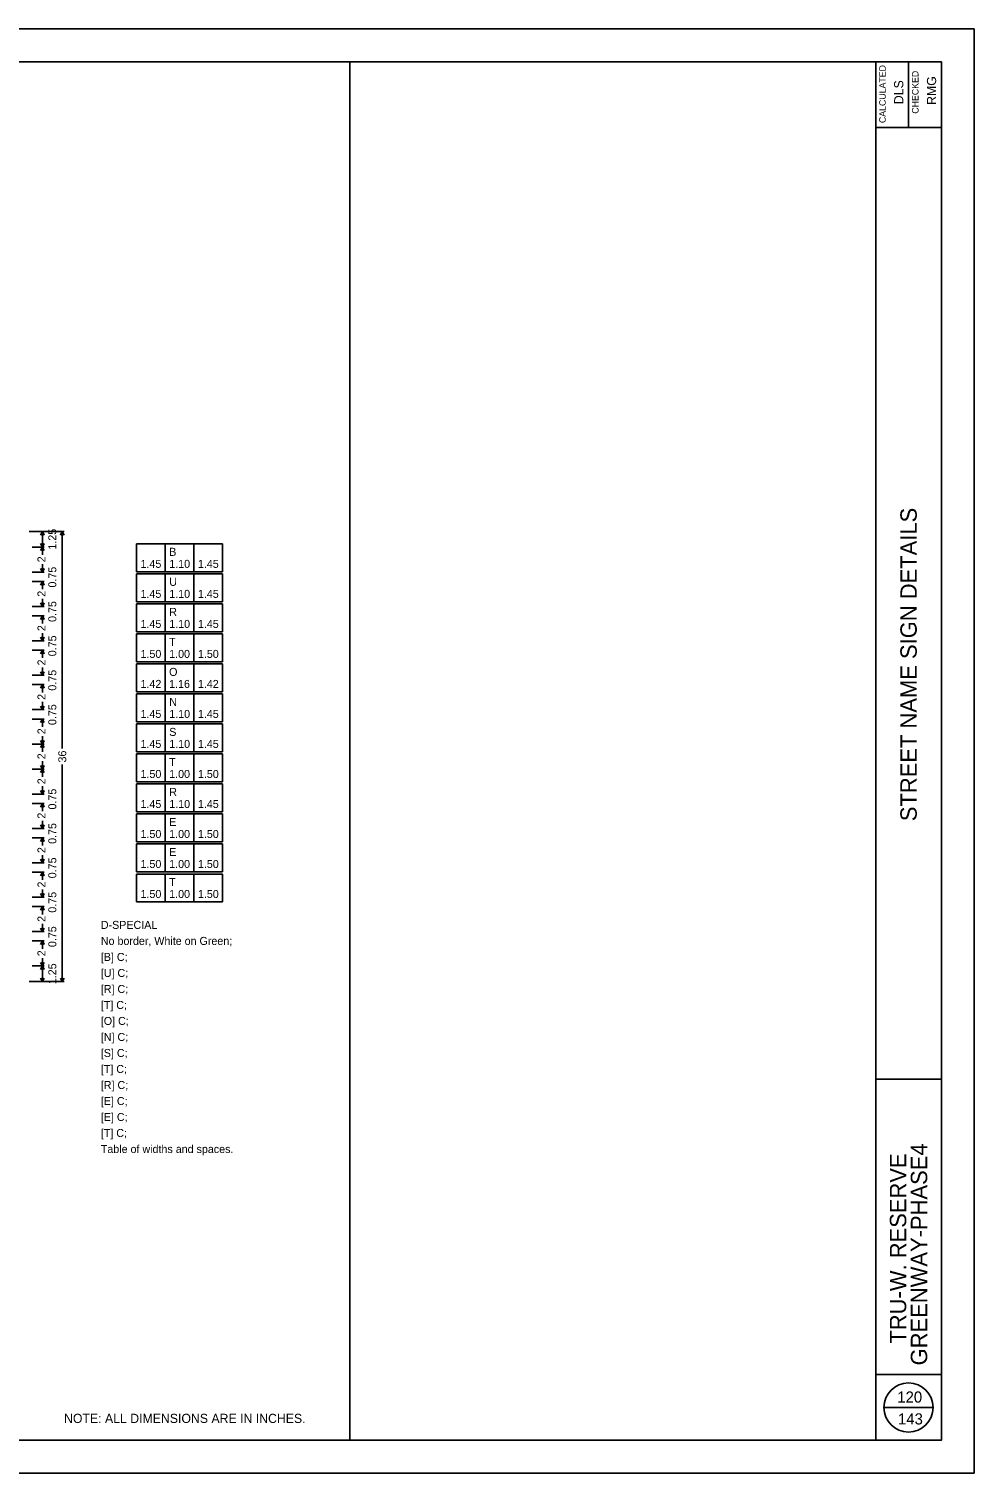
# Model space of a CAD drawing. Extents: x -16.4 to 26.5, y -12.9 to 9.1.
# Drawn here: x 3.22 to 17.63, y -12.91 to 9.09 of the extents above; entities that cross this region are included whole.
import ezdxf

# ---------------------------------------------------------------- set-up
doc = ezdxf.new("R2010")
doc.units = 0
for name, color, linetype in [('PM_P_Text', 7, 'Continuous'), ('SH_Border', 7, 'Continuous'), ('SH_Cut_Line', 7, 'Continuous'), ('SH_Data', 7, 'Continuous'), ('SH_Text', 7, 'Continuous')]:
    doc.layers.add(name, color=color, linetype=linetype)

msp = doc.modelspace()

# ---------------------------------------------------------------- linework, layer by layer
at = {"layer": 'SH_Border'}
for p, q in [((16.129, -12.407), (16.129, 8.593)), ((16.629, 8.593), (16.629, 7.593)), ((16.129, 7.593), (17.129, 7.593)), ((16.129, -6.907), (17.129, -6.907)), ((16.129, -11.407), (17.129, -11.407))]:
    msp.add_line(p, q, dxfattribs=at)
msp.add_lwpolyline([(-14.371, 8.593), (17.129, 8.593), (17.129, -12.407), (-14.371, -12.407)], close=True, dxfattribs=at)
at = {"layer": 'SH_Cut_Line'}
msp.add_lwpolyline([(-16.371, -12.907), (17.629, -12.907), (17.629, 9.093), (-16.371, 9.093)], close=True, dxfattribs=at)
at = {"layer": 'SH_Data'}
msp.add_line((16.254, -11.907), (17.004, -11.907), dxfattribs=at)
msp.add_circle((16.629, -11.907), 0.375, dxfattribs=at)
at = {"layer": 'SH_Text'}
for p, q in [((8.11, -12.407), (8.11, 8.593)), ((3.758, 1.438), (3.224, 1.438)), ((3.453, 1.438), (3.27, 1.438)), ((3.395, 1.383), (3.423, 1.438)), ((3.423, 1.318), (3.423, 1.438)), ((3.45, 1.383), (3.423, 1.438)), ((3.7, 1.383), (3.727, 1.438)), ((3.727, -1.87), (3.727, 1.438)), ((3.755, 1.383), (3.727, 1.438)), ((3.453, 1.199), (3.27, 1.199)), ((3.395, 1.254), (3.423, 1.199)), ((3.395, 1.145), (3.423, 1.199)), ((3.423, 1.318), (3.423, 1.199)), ((3.45, 1.254), (3.423, 1.199)), ((3.423, 1.081), (3.423, 1.199)), ((3.45, 1.145), (3.423, 1.199)), ((4.859, 1.249), (4.859, 0.822)), ((6.172, 1.249), (4.859, 1.249)), ((5.297, 1.249), (5.297, 0.822)), ((5.734, 1.249), (5.734, 0.822)), ((6.172, 1.249), (6.172, 0.822)), ((3.423, 0.937), (3.423, 0.818)), ((3.453, 0.818), (3.27, 0.818)), ((3.453, 0.676), (3.27, 0.676)), ((3.395, 0.873), (3.423, 0.818)), ((3.395, 0.621), (3.423, 0.676)), ((3.45, 0.873), (3.423, 0.818)), ((3.423, 0.557), (3.423, 0.676)), ((3.45, 0.621), (3.423, 0.676)), ((6.172, 0.822), (4.859, 0.822)), ((4.859, 0.791), (4.859, 0.365)), ((6.172, 0.791), (4.859, 0.791)), ((5.297, 0.791), (5.297, 0.365)), ((5.734, 0.791), (5.734, 0.365)), ((6.172, 0.791), (6.172, 0.365)), ((3.453, 0.295), (3.27, 0.295)), ((3.395, 0.349), (3.423, 0.295)), ((3.423, 0.413), (3.423, 0.295)), ((3.45, 0.349), (3.423, 0.295)), ((6.172, 0.365), (4.859, 0.365)), ((4.859, 0.334), (4.859, -0.092)), ((6.172, 0.334), (4.859, 0.334)), ((5.297, 0.334), (5.297, -0.092)), ((5.734, 0.334), (5.734, -0.092)), ((6.172, 0.334), (6.172, -0.092)), ((3.453, 0.152), (3.27, 0.152)), ((3.395, 0.097), (3.423, 0.152)), ((3.423, 0.033), (3.423, 0.152)), ((3.45, 0.097), (3.423, 0.152)), ((3.395, -0.175), (3.423, -0.229)), ((3.423, -0.111), (3.423, -0.229)), ((3.45, -0.175), (3.423, -0.229)), ((6.172, -0.092), (4.859, -0.092)), ((4.859, -0.123), (4.859, -0.55)), ((6.171, -0.123), (4.859, -0.123)), ((5.296, -0.123), (5.296, -0.55)), ((5.734, -0.123), (5.734, -0.55)), ((6.171, -0.123), (6.171, -0.55)), ((3.453, -0.229), (3.27, -0.229)), ((3.453, -0.372), (3.27, -0.372)), ((3.395, -0.427), (3.423, -0.372)), ((3.423, -0.49), (3.423, -0.372)), ((3.45, -0.427), (3.423, -0.372)), ((3.423, -0.635), (3.423, -0.753)), ((6.171, -0.55), (4.859, -0.55)), ((4.859, -0.58), (4.859, -1.007)), ((6.171, -0.58), (4.859, -0.58)), ((5.295, -0.58), (5.295, -1.007)), ((5.734, -0.58), (5.734, -1.007)), ((6.171, -0.58), (6.171, -1.007)), ((3.453, -0.753), (3.27, -0.753)), ((3.395, -0.699), (3.423, -0.753)), ((3.45, -0.699), (3.423, -0.753)), ((3.453, -0.896), (3.27, -0.896)), ((3.395, -0.951), (3.423, -0.896)), ((3.423, -1.014), (3.423, -0.896)), ((3.45, -0.951), (3.423, -0.896)), ((6.171, -1.007), (4.859, -1.007)), ((4.859, -1.037), (4.859, -1.464)), ((6.172, -1.037), (4.859, -1.037)), ((5.297, -1.037), (5.297, -1.464)), ((5.734, -1.037), (5.734, -1.464)), ((6.172, -1.037), (6.172, -1.464)), ((3.453, -1.277), (3.27, -1.277)), ((3.395, -1.223), (3.423, -1.277)), ((3.423, -1.159), (3.423, -1.277)), ((3.45, -1.223), (3.423, -1.277)), ((3.453, -1.42), (3.27, -1.42)), ((3.395, -1.474), (3.423, -1.42)), ((3.423, -1.538), (3.423, -1.42)), ((3.45, -1.474), (3.423, -1.42)), ((6.172, -1.464), (4.859, -1.464)), ((4.859, -1.495), (4.859, -1.921)), ((6.172, -1.495), (4.859, -1.495)), ((5.297, -1.495), (5.297, -1.921)), ((5.734, -1.495), (5.734, -1.921)), ((6.172, -1.495), (6.172, -1.921)), ((3.395, -1.746), (3.423, -1.801)), ((3.423, -1.683), (3.423, -1.801)), ((3.45, -1.746), (3.423, -1.801)), ((3.453, -1.801), (3.27, -1.801)), ((3.395, -1.855), (3.423, -1.801)), ((3.423, -1.919), (3.423, -1.801)), ((3.45, -1.855), (3.423, -1.801)), ((6.172, -1.921), (4.859, -1.921)), ((4.859, -1.952), (4.859, -2.378)), ((6.171, -1.952), (4.859, -1.952)), ((5.296, -1.952), (5.296, -2.378)), ((5.734, -1.952), (5.734, -2.378)), ((6.171, -1.952), (6.171, -2.378)), ((3.453, -2.182), (3.27, -2.182)), ((3.395, -2.127), (3.423, -2.182)), ((3.395, -2.236), (3.423, -2.182)), ((3.423, -2.064), (3.423, -2.182)), ((3.45, -2.127), (3.423, -2.182)), ((3.423, -2.3), (3.423, -2.182)), ((3.45, -2.236), (3.423, -2.182)), ((3.727, -2.113), (3.727, -5.42)), ((6.171, -2.378), (4.859, -2.378)), ((4.859, -2.409), (4.859, -2.836)), ((6.172, -2.409), (4.859, -2.409)), ((5.297, -2.409), (5.297, -2.836)), ((5.734, -2.409), (5.734, -2.836)), ((6.172, -2.409), (6.172, -2.836)), ((3.453, -2.563), (3.27, -2.563)), ((3.395, -2.508), (3.423, -2.563)), ((3.423, -2.445), (3.423, -2.563)), ((3.45, -2.508), (3.423, -2.563)), ((3.453, -2.706), (3.27, -2.706)), ((3.395, -2.76), (3.423, -2.706)), ((3.423, -2.824), (3.423, -2.706)), ((3.45, -2.76), (3.423, -2.706)), ((6.172, -2.836), (4.859, -2.836)), ((3.395, -3.032), (3.423, -3.087)), ((3.423, -2.969), (3.423, -3.087)), ((3.45, -3.032), (3.423, -3.087)), ((4.859, -2.866), (4.859, -3.293)), ((6.171, -2.866), (4.859, -2.866)), ((5.296, -2.866), (5.296, -3.293)), ((5.734, -2.866), (5.734, -3.293)), ((6.171, -2.866), (6.171, -3.293)), ((3.453, -3.087), (3.27, -3.087)), ((3.453, -3.23), (3.27, -3.23)), ((3.395, -3.284), (3.423, -3.23)), ((3.423, -3.348), (3.423, -3.23)), ((3.45, -3.284), (3.423, -3.23)), ((6.171, -3.293), (4.859, -3.293)), ((3.423, -3.492), (3.423, -3.611)), ((4.859, -3.323), (4.859, -3.75)), ((6.171, -3.323), (4.859, -3.323)), ((5.296, -3.323), (5.296, -3.75)), ((5.734, -3.323), (5.734, -3.75)), ((6.171, -3.323), (6.171, -3.75)), ((3.453, -3.611), (3.27, -3.611)), ((3.395, -3.556), (3.423, -3.611)), ((3.45, -3.556), (3.423, -3.611)), ((3.453, -3.754), (3.27, -3.754)), ((3.395, -3.808), (3.423, -3.754)), ((3.423, -3.872), (3.423, -3.754)), ((3.45, -3.808), (3.423, -3.754)), ((6.171, -3.75), (4.859, -3.75)), ((4.859, -3.781), (4.859, -4.207)), ((6.171, -3.781), (4.859, -3.781)), ((5.296, -3.781), (5.296, -4.207)), ((5.734, -3.781), (5.734, -4.207)), ((6.171, -3.781), (6.171, -4.207)), ((3.453, -4.135), (3.27, -4.135)), ((3.395, -4.08), (3.423, -4.135)), ((3.423, -4.016), (3.423, -4.135)), ((3.45, -4.08), (3.423, -4.135)), ((3.453, -4.277), (3.27, -4.277)), ((3.395, -4.332), (3.423, -4.277)), ((3.423, -4.396), (3.423, -4.277)), ((3.45, -4.332), (3.423, -4.277)), ((6.171, -4.207), (4.859, -4.207)), ((3.395, -4.604), (3.423, -4.658)), ((3.423, -4.54), (3.423, -4.658)), ((3.45, -4.604), (3.423, -4.658)), ((3.453, -4.658), (3.27, -4.658)), ((3.453, -4.801), (3.27, -4.801)), ((3.395, -4.856), (3.423, -4.801)), ((3.423, -4.92), (3.423, -4.801)), ((3.45, -4.856), (3.423, -4.801)), ((3.453, -5.182), (3.27, -5.182)), ((3.453, -5.182), (3.27, -5.182)), ((3.395, -5.128), (3.423, -5.182)), ((3.395, -5.237), (3.423, -5.182)), ((3.423, -5.064), (3.423, -5.182)), ((3.45, -5.128), (3.423, -5.182)), ((3.423, -5.301), (3.423, -5.182)), ((3.45, -5.237), (3.423, -5.182)), ((3.758, -5.42), (3.224, -5.42)), ((3.453, -5.42), (3.27, -5.42)), ((3.395, -5.366), (3.423, -5.42)), ((3.423, -5.301), (3.423, -5.42)), ((3.45, -5.366), (3.423, -5.42)), ((3.7, -5.366), (3.727, -5.42)), ((3.755, -5.366), (3.727, -5.42))]:
    msp.add_line(p, q, dxfattribs=at)

# ---------------------------------------------------------------- texts
at = {"layer": 'PM_P_Text'}
msp.add_text('NOTE: ALL DIMENSIONS ARE IN INCHES.', height=0.14, dxfattribs=at).set_placement((3.754, -12.143))
at = {"layer": 'SH_Data'}
for s, height, p in [('CALCULATED', 0.1, (16.281, 7.658)), ('CHECKED', 0.1, (16.781, 7.801)), ('DLS', 0.14, (16.549, 7.946)), ('RMG', 0.14, (17.049, 7.935)), ('STREET NAME SIGN DETAILS', 0.25, (16.754, -2.976)), ('GREENWAY-PHASE4', 0.25, (16.913, -11.266)), ('TRU-W. RESERVE', 0.25, (16.594, -10.934))]:
    msp.add_text(s, height=height, rotation=90, dxfattribs=at).set_placement(p)
msp.add_text('143', height=0.17, dxfattribs=at).set_placement((16.468, -12.166))
at = {"layer": 'SH_Text'}
for s, height, p in [('1.25', 0.1219, (3.636, 1.161)), ('2', 0.122, (3.471, 0.967)), ('0.75', 0.1219, (3.636, 0.583)), ('2', 0.122, (3.471, 0.443)), ('0.75', 0.1219, (3.636, 0.059)), ('2', 0.122, (3.471, -0.081)), ('0.75', 0.1219, (3.636, -0.464)), ('2', 0.122, (3.471, -0.604)), ('0.75', 0.1219, (3.636, -0.988)), ('2', 0.122, (3.471, -1.128)), ('0.75', 0.1219, (3.636, -1.512)), ('2', 0.122, (3.471, -1.652)), ('2', 0.122, (3.471, -2.033)), ('36', 0.1219, (3.788, -2.082)), ('2', 0.122, (3.471, -2.414)), ('0.75', 0.1219, (3.636, -2.798)), ('2', 0.122, (3.471, -2.938)), ('0.75', 0.1219, (3.636, -3.322)), ('2', 0.122, (3.471, -3.462)), ('0.75', 0.1219, (3.636, -3.846)), ('2', 0.122, (3.471, -3.986)), ('0.75', 0.1219, (3.636, -4.37)), ('2', 0.122, (3.471, -4.51)), ('0.75', 0.1219, (3.636, -4.894)), ('2', 0.122, (3.471, -5.034)), ('1.25', 0.1219, (3.636, -5.459))]:
    msp.add_text(s, height=height, rotation=90.0002, dxfattribs=at).set_placement(p)
for s, height, p in [('B', 0.122, (5.358, 1.066)), ('1.45', 0.1219, (4.92, 0.883)), ('1.10', 0.1219, (5.358, 0.883)), ('1.45', 0.1219, (5.795, 0.883)), ('U', 0.122, (5.358, 0.609)), ('1.45', 0.1219, (4.92, 0.426)), ('1.10', 0.1219, (5.358, 0.426)), ('1.45', 0.1219, (5.795, 0.426)), ('R', 0.122, (5.358, 0.151)), ('1.45', 0.1219, (4.92, -0.032)), ('1.10', 0.1219, (5.358, -0.032)), ('1.45', 0.1219, (5.795, -0.032)), ('T', 0.122, (5.357, -0.306)), ('1.50', 0.1219, (4.92, -0.489)), ('1.00', 0.1219, (5.357, -0.489)), ('1.50', 0.1219, (5.795, -0.489)), ('O', 0.122, (5.356, -0.763)), ('1.42', 0.1219, (4.92, -0.946)), ('1.16', 0.1219, (5.356, -0.946)), ('1.42', 0.1219, (5.795, -0.946)), ('N', 0.122, (5.358, -1.22)), ('1.45', 0.1219, (4.92, -1.403)), ('1.10', 0.1219, (5.358, -1.403)), ('1.45', 0.1219, (5.795, -1.403)), ('1.45', 0.1219, (4.92, -1.86)), ('S', 0.122, (5.358, -1.677)), ('1.10', 0.1219, (5.358, -1.86)), ('1.45', 0.1219, (5.795, -1.86)), ('1.50', 0.1219, (4.92, -2.318)), ('T', 0.122, (5.357, -2.135)), ('1.00', 0.1219, (5.357, -2.318)), ('1.50', 0.1219, (5.795, -2.318)), ('R', 0.122, (5.358, -2.592)), ('1.45', 0.1219, (4.92, -2.775)), ('1.10', 0.1219, (5.358, -2.775)), ('1.45', 0.1219, (5.795, -2.775)), ('E', 0.122, (5.357, -3.049)), ('1.50', 0.1219, (4.92, -3.232)), ('1.00', 0.1219, (5.357, -3.232)), ('1.50', 0.1219, (5.795, -3.232)), ('E', 0.122, (5.357, -3.506)), ('1.50', 0.1219, (4.92, -3.689)), ('1.00', 0.1219, (5.357, -3.689)), ('1.50', 0.1219, (5.795, -3.689)), ('T', 0.122, (5.357, -3.963)), ('1.50', 0.1219, (4.92, -4.146)), ('1.00', 0.1219, (5.357, -4.146)), ('1.50', 0.1219, (5.795, -4.146)), ('D-SPECIAL', 0.1219, (4.315, -4.617)), ('No border, White on Green; ', 0.12192, (4.315, -4.861)), ('[B] C; ', 0.1219, (4.315, -5.105)), ('[U] C; ', 0.1219, (4.315, -5.349)), ('[R] C; ', 0.1219, (4.315, -5.593)), ('[T] C; ', 0.1219, (4.315, -5.837)), ('[O] C; ', 0.1219, (4.315, -6.08)), ('[N] C; ', 0.1219, (4.315, -6.324)), ('[S] C; ', 0.1219, (4.315, -6.568)), ('[T] C; ', 0.1219, (4.315, -6.812)), ('[R] C; ', 0.1219, (4.315, -7.056)), ('[E] C; ', 0.1219, (4.315, -7.3)), ('[E] C; ', 0.1219, (4.315, -7.543)), ('[T] C; ', 0.1219, (4.315, -7.787)), ('Table of widths and spaces.', 0.12192, (4.315, -8.031)), ('120', 0.17, (16.457, -11.833))]:
    msp.add_text(s, height=height, dxfattribs=at).set_placement(p)

doc.saveas('drawing.dxf')
